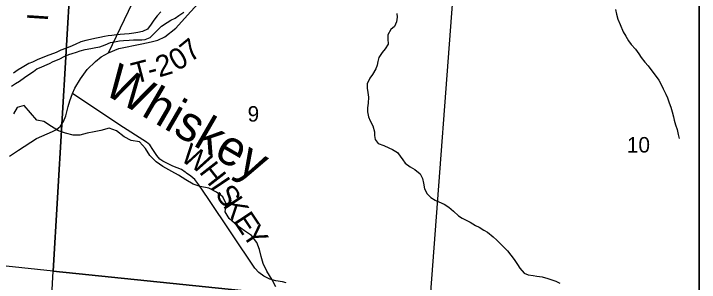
# Model space of a CAD drawing. Extents: x 5.6 to 39.6, y 0.7 to 22.7.
# Drawn here: x 13.207 to 15.052, y 19.086 to 19.81 of the extents above; entities that cross this region are included whole.
import ezdxf

# ---------------------------------------------------------------- set-up
doc = ezdxf.new("R2010")
doc.units = 0
doc.layers.add('Default', color=7, linetype='Continuous')
doc.layers.add('SH_Data', color=7, linetype='Continuous')

msp = doc.modelspace()

# ---------------------------------------------------------------- linework, layer by layer
at = {"layer": 'Default'}
msp.add_line((15.0518, 18.9873), (15.0518, 19.9373), dxfattribs=at)
for points in [[(15.0518, 18.0251), (15.0518, 21.7074), (8.2518, 21.7074), (8.2518, 18.5322)], [(15.0518, 18.0251), (15.0518, 21.7074), (8.2518, 21.7074), (8.2518, 18.5322)], [(15.0518, 18.0251), (15.0518, 21.7074), (10.4881, 21.7074)], [(13.462, 19.7051), (13.6117, 20.0185), (13.6298, 20.0515), (13.6607, 20.1075), (13.6872, 20.1543), (13.7228, 20.2174), (13.7419, 20.2532)], [(15.0518, 19.9373), (14.3975, 19.9797), (14.3249, 19.0118), (15.0518, 18.9873)], [(13.462, 19.7051), (13.4896, 19.7162), (13.5513, 19.7295), (13.5763, 19.7344), (13.5941, 19.7394), (13.613, 19.7481), (13.6433, 19.7716), (13.6739, 19.8066), (13.6932, 19.8274), (13.7352, 19.8684), (13.799, 19.9325), (13.8175, 19.9457)], [(14.826, 19.8221), (14.8292, 19.8092), (14.8325, 19.7959), (14.8384, 19.7814), (14.8472, 19.7616), (14.8542, 19.7497), (14.8617, 19.7375), (14.868, 19.7272), (14.8799, 19.7145), (14.8889, 19.7023), (14.8956, 19.692), (14.9049, 19.6797), (14.9138, 19.6701), (14.9217, 19.6602), (14.9302, 19.6479), (14.9429, 19.6315), (14.9488, 19.62), (14.9544, 19.6082), (14.9614, 19.5937)], [(13.201, 19.6154), (13.2117, 19.6225), (13.222, 19.6288), (13.2354, 19.6382), (13.2472, 19.6464), (13.2595, 19.6549), (13.269, 19.6617), (13.2808, 19.6664), (13.2904, 19.6705), (13.3029, 19.6764), (13.3128, 19.6812), (13.3285, 19.6882), (13.3445, 19.696), (13.3547, 19.7004), (13.3642, 19.7034), (13.3753, 19.707), (13.3852, 19.7107), (13.3988, 19.7143), (13.4144, 19.7168), (13.4277, 19.7189), (13.4383, 19.7214), (13.4531, 19.7265), (13.4672, 19.7328), (13.4782, 19.7349), (13.4915, 19.7374), (13.5021, 19.7384), (13.5169, 19.7394), (13.529, 19.7396), (13.5385, 19.7403), (13.551, 19.7401), (13.5605, 19.7408), (13.5734, 19.7463), (13.583, 19.7553), (13.5945, 19.7673), (13.6045, 19.777), (13.6194, 19.7863), (13.6297, 19.7926), (13.6407, 19.7986), (13.6514, 19.8052), (13.664, 19.815)], [(13.6027, 19.8153), (13.5931, 19.8048), (13.5839, 19.7928), (13.5769, 19.7819), (13.5669, 19.7691), (13.5532, 19.7621), (13.541, 19.7596), (13.5296, 19.7582), (13.5175, 19.7565), (13.505, 19.7555), (13.4929, 19.7541), (13.4834, 19.7535), (13.4709, 19.7521), (13.461, 19.7507), (13.4512, 19.7486), (13.4383, 19.7465), (13.4246, 19.7432), (13.4132, 19.7411), (13.4011, 19.7386), (13.387, 19.7346), (13.3718, 19.7275), (13.3573, 19.7213), (13.3459, 19.7165), (13.3337, 19.7117), (13.3204, 19.7062), (13.2937, 19.6959), (13.2831, 19.6918), (13.2713, 19.6867), (13.2568, 19.6796), (13.2473, 19.6763), (13.2297, 19.6656), (13.2186, 19.6589), (13.206, 19.6503)], [(14.2375, 19.8108), (14.2385, 19.8013), (14.2368, 19.7888), (14.2314, 19.776), (14.2214, 19.7678), (14.2136, 19.7531), (14.2131, 19.7428), (14.2141, 19.7284), (14.206, 19.7156), (14.1983, 19.7055), (14.189, 19.6927), (14.1862, 19.6817), (14.1846, 19.6719), (14.1814, 19.6617), (14.1725, 19.6463), (14.1652, 19.6365), (14.1578, 19.6218), (14.1577, 19.6093), (14.1598, 19.5979), (14.1611, 19.585), (14.1602, 19.569), (14.1589, 19.5569), (14.1587, 19.5455), (14.1612, 19.5322), (14.166, 19.5212), (14.1727, 19.5082), (14.1778, 19.4922), (14.178, 19.482), (14.179, 19.4717), (14.1879, 19.4602), (14.203, 19.4551), (14.2162, 19.4489), (14.2264, 19.4446), (14.2391, 19.4361), (14.254, 19.4169), (14.26, 19.4074), (14.2735, 19.3973), (14.2866, 19.3904), (14.3001, 19.3792), (14.3064, 19.3662), (14.3096, 19.3533), (14.3125, 19.3381), (14.3191, 19.3247), (14.3296, 19.3151), (14.3405, 19.3082), (14.3507, 19.3031), (14.3654, 19.2972), (14.3774, 19.2888), (14.3901, 19.278), (14.4036, 19.2653), (14.4133, 19.2591), (14.4239, 19.2537), (14.4352, 19.2482), (14.4498, 19.2397), (14.4596, 19.235), (14.4716, 19.2273), (14.4822, 19.2211), (14.4972, 19.2092), (14.5069, 19.1996), (14.5203, 19.1861), (14.5357, 19.1715), (14.545, 19.1597), (14.5532, 19.1482), (14.5621, 19.1348), (14.5684, 19.1245), (14.5807, 19.1107), (14.5909, 19.1068), (14.6045, 19.1043), (14.6144, 19.1031), (14.6291, 19.1014), (14.6442, 19.0963), (14.6551, 19.0931), (14.6657, 19.0896), (14.6762, 19.0841)], [(13.1954, 19.426), (13.2193, 19.4423), (13.2682, 19.4736), (13.3113, 19.4932), (13.32, 19.497), (13.326, 19.5016), (13.3324, 19.5069), (13.3409, 19.52), (13.3466, 19.5352), (13.353, 19.5601), (13.3577, 19.5755), (13.3646, 19.595), (13.3711, 19.6094), (13.3859, 19.6349), (13.404, 19.6596), (13.4264, 19.682), (13.4423, 19.6938), (13.462, 19.7051)], [(13.6682, 19.3832), (13.658, 19.39), (13.6347, 19.3991), (13.6201, 19.4062), (13.6081, 19.4125), (13.5999, 19.4179), (13.5917, 19.4279), (13.5807, 19.4441), (13.5726, 19.4571), (13.5644, 19.4637), (13.4918, 19.5101), (13.3646, 19.595)], [(14.9614, 19.5937), (14.9658, 19.5838), (14.9709, 19.5697), (14.9749, 19.5583), (14.979, 19.5457), (14.9822, 19.5328), (14.9844, 19.5233), (14.988, 19.5111), (14.9924, 19.4982), (14.9952, 19.4849), (14.9974, 19.4742)], [(13.912, 19.0746), (13.9023, 19.0929), (13.8881, 19.1165), (13.8776, 19.1372), (13.8724, 19.1562), (13.868, 19.1752), (13.8613, 19.1935), (13.847, 19.2126), (13.8274, 19.2249), (13.8078, 19.2395), (13.7867, 19.258), (13.7754, 19.2763), (13.7786, 19.2983), (13.7697, 19.3166), (13.7523, 19.3297), (13.7319, 19.3405), (13.7084, 19.3445), (13.6895, 19.3507), (13.6699, 19.3623), (13.6503, 19.3753), (13.6321, 19.3846), (13.608, 19.3985), (13.5899, 19.4108), (13.5726, 19.4284), (13.5613, 19.4467), (13.5448, 19.4651), (13.5228, 19.4683), (13.5039, 19.4784), (13.4836, 19.4945), (13.4639, 19.5023), (13.4411, 19.4956), (13.4229, 19.492), (13.4039, 19.4883), (13.3849, 19.4832), (13.3667, 19.4833), (13.3455, 19.4888), (13.3274, 19.4943), (13.3085, 19.5066), (13.2874, 19.5197), (13.2684, 19.5236), (13.2519, 19.5428), (13.2346, 19.5627), (13.2156, 19.5575), (13.2056, 19.5401)], [(13.94, 19.0853), (13.9299, 19.0874), (13.9117, 19.0907), (13.8963, 19.0948), (13.8802, 19.1027), (13.866, 19.1128), (13.8552, 19.1243), (13.7296, 19.3121), (13.7049, 19.3489), (13.6938, 19.3635), (13.6834, 19.3724), (13.6715, 19.381), (13.6698, 19.3821), (13.6682, 19.3832)]]:
    msp.add_lwpolyline(points, dxfattribs=at)
for points in [[(12.7, 20.1814), (13.3714, 20.1056), (13.3131, 19.1164), (12.8136, 19.1696), (12.427, 19.2046), (12.4531, 19.8481)], [(13.3714, 20.1056), (14.3975, 19.9797), (14.3249, 19.0118), (13.3131, 19.1164)], [(13.3131, 19.1164), (14.3249, 19.0118), (14.2605, 18.0881), (13.2617, 18.164)]]:
    msp.add_lwpolyline(points, close=True, dxfattribs=at)
at = {"layer": 'SH_Data'}
msp.add_line((15.0518, 21.7074), (15.0518, 14.7074), dxfattribs=at)

# ---------------------------------------------------------------- texts
at = {"layer": 'Default'}
for s, height, rotation, p in [('I', 0.0565, 86.2521, (13.2985, 19.789)), ('7', 0.0568, 39.2328, (13.6831, 19.6776)), ('0', 0.0568, 30.4422, (13.6452, 19.6544)), ('2', 0.0568, 16.7018, (13.5981, 19.6384)), ('Whiskey', 0.09465, 329.9217, (13.4439, 19.5973)), ('T', 0.0568, 14.6516, (13.5323, 19.6211)), ('-', 0.0568, 14.9671, (13.5737, 19.6319)), ('9', 0.0418, 0, (13.8361, 19.5195)), ('10', 0.04182, 0, (14.8569, 19.4361)), ('W', 0.0568, 326.9277, (13.6523, 19.416)), ('H', 0.0568, 307.9566, (13.7038, 19.3835)), ('I', 0.0568, 303.846, (13.734, 19.3449)), ('S', 0.0568, 303.6967, (13.7469, 19.3256)), ('K', 0.0568, 303.687, (13.7682, 19.2937)), ('E', 0.0568, 303.6897, (13.7959, 19.2521)), ('Y', 0.0568, 303.687, (13.8195, 19.2167))]:
    msp.add_text(s, height=height, rotation=rotation, dxfattribs=at).set_placement(p)

doc.saveas('drawing.dxf')
